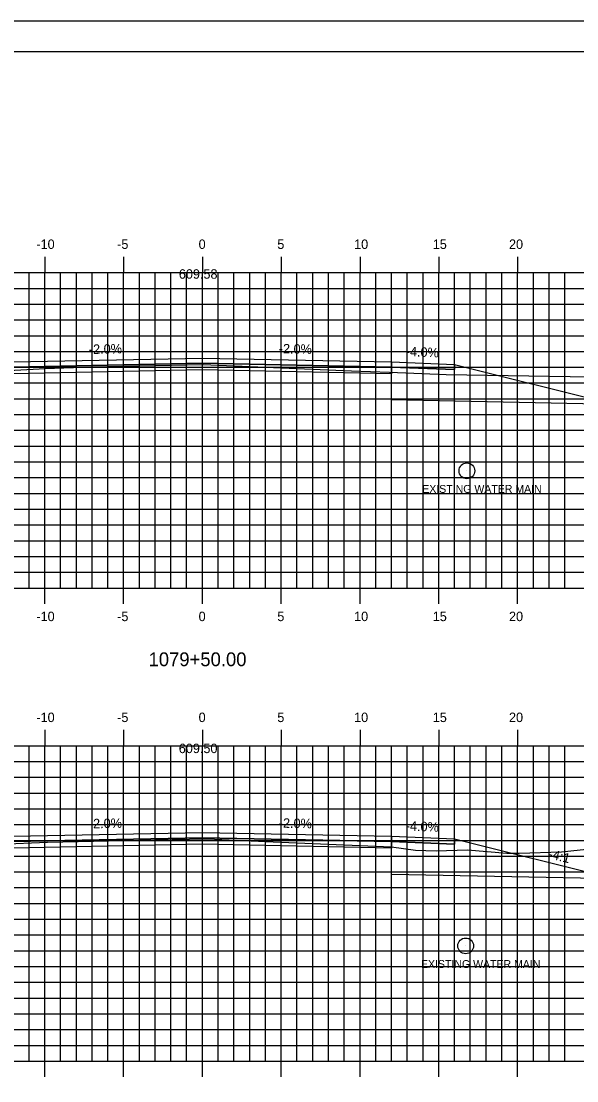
# Model space of a CAD drawing. Extents: x 1070760 to 1070930, y 779716 to 779826.
# Drawn here: x 1070831.4 to 1070866.6, y 779758.5 to 779825.6 of the extents above; entities that cross this region are included whole.
import ezdxf

# ---------------------------------------------------------------- set-up
doc = ezdxf.new("R2010")
doc.units = 0
for name, color, linetype in [('ANNOTATION', 7, 'Continuous'), ('BORDER', 7, 'Continuous'), ('D_Roadway_Centerline', 7, 'Continuous'), ('D_Roadway_Centerline_Text', 7, 'Continuous'), ('D_Roadway_Edge_Pavement', 7, 'Continuous'), ('D_Roadway_Edge_Shoulder', 7, 'Continuous'), ('D_Roadway_Pavement', 7, 'Continuous'), ('D_Roadway_SubGrade', 7, 'Continuous'), ('D_Text_Monospaced', 7, 'Continuous'), ('Existing Water Main', 7, 'Continuous'), ('H_V ANNOTATION', 7, 'Continuous'), ('MAJOR', 7, 'Continuous'), ('MINOR', 7, 'Continuous'), ('PLOT BOUNDARY', 7, 'Continuous'), ('S_Roadway_Centerline', 7, 'Continuous')]:
    doc.layers.add(name, color=color, linetype=linetype)

msp = doc.modelspace()

# ---------------------------------------------------------------- linework, layer by layer
at = {"layer": 'BORDER'}
msp.add_lwpolyline([(1070767.881, 779718.706), (1070927.881, 779718.706), (1070927.881, 779823.706), (1070767.881, 779823.706)], close=True, dxfattribs=at)
at = {"layer": 'D_Roadway_Centerline'}
msp.add_lwpolyline([(1070826.881, 779773.806), (1070830.881, 779773.966), (1070842.881, 779774.206), (1070854.881, 779773.966), (1070858.881, 779773.806)], dxfattribs=at)
at = {"layer": 'D_Roadway_Edge_Pavement'}
for points in [[(1070830.881, 779803.713), (1070830.881, 779804.046), (1070842.881, 779804.286), (1070854.881, 779804.046), (1070854.881, 779803.713), (1070842.881, 779803.953)], [(1070830.881, 779773.633), (1070830.881, 779773.966), (1070842.881, 779774.206), (1070854.881, 779773.966), (1070854.881, 779773.633), (1070842.881, 779773.873)]]:
    msp.add_lwpolyline(points, close=True, dxfattribs=at)
at = {"layer": 'D_Roadway_Edge_Shoulder'}
for points in [[(1070854.881, 779804.046), (1070858.881, 779803.886), (1070858.881, 779803.553), (1070854.881, 779803.713)], [(1070854.881, 779773.966), (1070858.881, 779773.806), (1070858.881, 779773.473), (1070854.881, 779773.633)]]:
    msp.add_lwpolyline(points, close=True, dxfattribs=at)
at = {"layer": 'D_Roadway_Pavement'}
for points in [[(1070830.881, 779803.296), (1070830.881, 779803.713), (1070842.881, 779803.953), (1070854.881, 779803.713), (1070854.881, 779803.296), (1070842.881, 779803.536)], [(1070830.881, 779773.216), (1070830.881, 779773.633), (1070842.881, 779773.873), (1070854.881, 779773.633), (1070854.881, 779773.216), (1070842.881, 779773.456)]]:
    msp.add_lwpolyline(points, close=True, dxfattribs=at)
at = {"layer": 'D_Roadway_SubGrade'}
for points in [[(1070854.881, 779802.213), (1070854.881, 779803.713), (1070854.881, 779803.713), (1070858.881, 779803.553), (1070858.881, 779803.886), (1070869.04, 779801.347), (1070854.881, 779801.63)], [(1070854.881, 779772.133), (1070854.881, 779773.633), (1070854.881, 779773.633), (1070858.881, 779773.473), (1070858.881, 779773.806), (1070869.04, 779771.266), (1070854.881, 779771.549)]]:
    msp.add_lwpolyline(points, close=True, dxfattribs=at)
at = {"layer": 'Existing Water Main'}
for points in [[(1070859.664, 779797.14), (1070859.664, 779797.14)], [(1070859.582, 779767.013), (1070859.582, 779767.013)]]:
    msp.add_lwpolyline(points, dxfattribs=at)
for centre in [(1070859.664, 779797.14), (1070859.582, 779767.013)]:
    msp.add_circle(centre, 0.501, dxfattribs=at)
at = {"layer": 'MAJOR'}
for p, q in [((1070832.881, 779810.708), (1070832.881, 779809.706)), ((1070837.881, 779810.708), (1070837.881, 779809.706)), ((1070842.881, 779810.708), (1070842.881, 779809.706)), ((1070847.881, 779810.708), (1070847.881, 779809.706)), ((1070852.881, 779810.708), (1070852.881, 779809.706)), ((1070857.881, 779810.708), (1070857.881, 779809.706)), ((1070862.881, 779810.708), (1070862.881, 779809.706)), ((1070772.881, 779809.706), (1070912.881, 779809.706)), ((1070772.881, 779809.706), (1070912.881, 779809.706)), ((1070832.881, 779789.706), (1070832.881, 779809.706)), ((1070837.881, 779789.706), (1070837.881, 779809.706)), ((1070842.881, 779789.706), (1070842.881, 779809.706)), ((1070847.881, 779789.706), (1070847.881, 779809.706)), ((1070852.881, 779789.706), (1070852.881, 779809.706)), ((1070857.881, 779789.706), (1070857.881, 779809.706)), ((1070862.881, 779789.706), (1070862.881, 779809.706)), ((1070772.881, 779804.706), (1070912.881, 779804.706)), ((1070772.881, 779799.706), (1070912.881, 779799.706)), ((1070772.881, 779794.706), (1070912.881, 779794.706)), ((1070772.881, 779789.706), (1070912.881, 779789.706)), ((1070772.881, 779789.706), (1070912.881, 779789.706)), ((1070832.881, 779788.704), (1070832.881, 779789.706)), ((1070837.881, 779788.704), (1070837.881, 779789.706)), ((1070842.881, 779788.704), (1070842.881, 779789.706)), ((1070847.881, 779788.704), (1070847.881, 779789.706)), ((1070852.881, 779788.704), (1070852.881, 779789.706)), ((1070857.881, 779788.704), (1070857.881, 779789.706)), ((1070862.881, 779788.704), (1070862.881, 779789.706)), ((1070832.881, 779780.708), (1070832.881, 779779.706)), ((1070837.881, 779780.708), (1070837.881, 779779.706)), ((1070842.881, 779780.708), (1070842.881, 779779.706)), ((1070847.881, 779780.708), (1070847.881, 779779.706)), ((1070852.881, 779780.708), (1070852.881, 779779.706)), ((1070857.881, 779780.708), (1070857.881, 779779.706)), ((1070862.881, 779780.708), (1070862.881, 779779.706)), ((1070772.881, 779779.706), (1070912.881, 779779.706)), ((1070772.881, 779779.706), (1070912.881, 779779.706)), ((1070832.881, 779759.706), (1070832.881, 779779.706)), ((1070837.881, 779759.706), (1070837.881, 779779.706)), ((1070842.881, 779759.706), (1070842.881, 779779.706)), ((1070847.881, 779759.706), (1070847.881, 779779.706)), ((1070852.881, 779759.706), (1070852.881, 779779.706)), ((1070857.881, 779759.706), (1070857.881, 779779.706)), ((1070862.881, 779759.706), (1070862.881, 779779.706)), ((1070772.881, 779774.706), (1070912.881, 779774.706)), ((1070772.881, 779769.706), (1070912.881, 779769.706)), ((1070772.881, 779764.706), (1070912.881, 779764.706)), ((1070772.881, 779759.706), (1070912.881, 779759.706)), ((1070772.881, 779759.706), (1070912.881, 779759.706)), ((1070832.881, 779758.704), (1070832.881, 779759.706)), ((1070837.881, 779758.704), (1070837.881, 779759.706)), ((1070842.881, 779758.704), (1070842.881, 779759.706)), ((1070847.881, 779758.704), (1070847.881, 779759.706)), ((1070852.881, 779758.704), (1070852.881, 779759.706)), ((1070857.881, 779758.704), (1070857.881, 779759.706)), ((1070862.881, 779758.704), (1070862.881, 779759.706))]:
    msp.add_line(p, q, dxfattribs=at)
at = {"layer": 'MINOR'}
for p, q in [((1070831.881, 779789.706), (1070831.881, 779809.706)), ((1070833.881, 779789.706), (1070833.881, 779809.706)), ((1070834.881, 779789.706), (1070834.881, 779809.706)), ((1070835.881, 779789.706), (1070835.881, 779809.706)), ((1070836.881, 779789.706), (1070836.881, 779809.706)), ((1070838.881, 779789.706), (1070838.881, 779809.706)), ((1070839.881, 779789.706), (1070839.881, 779809.706)), ((1070840.881, 779789.706), (1070840.881, 779809.706)), ((1070841.881, 779789.706), (1070841.881, 779809.706)), ((1070843.881, 779789.706), (1070843.881, 779809.706)), ((1070844.881, 779789.706), (1070844.881, 779809.706)), ((1070845.881, 779789.706), (1070845.881, 779809.706)), ((1070846.881, 779789.706), (1070846.881, 779809.706)), ((1070848.881, 779789.706), (1070848.881, 779809.706)), ((1070849.881, 779789.706), (1070849.881, 779809.706)), ((1070850.881, 779789.706), (1070850.881, 779809.706)), ((1070851.881, 779789.706), (1070851.881, 779809.706)), ((1070853.881, 779789.706), (1070853.881, 779809.706)), ((1070854.881, 779789.706), (1070854.881, 779809.706)), ((1070855.881, 779789.706), (1070855.881, 779809.706)), ((1070856.881, 779789.706), (1070856.881, 779809.706)), ((1070858.881, 779789.706), (1070858.881, 779809.706)), ((1070859.881, 779789.706), (1070859.881, 779809.706)), ((1070860.881, 779789.706), (1070860.881, 779809.706)), ((1070861.881, 779789.706), (1070861.881, 779809.706)), ((1070863.881, 779789.706), (1070863.881, 779809.706)), ((1070864.881, 779789.706), (1070864.881, 779809.706)), ((1070865.881, 779789.706), (1070865.881, 779809.706)), ((1070772.881, 779808.706), (1070912.881, 779808.706)), ((1070772.881, 779807.706), (1070912.881, 779807.706)), ((1070772.881, 779806.706), (1070912.881, 779806.706)), ((1070772.881, 779805.706), (1070912.881, 779805.706)), ((1070772.881, 779803.706), (1070912.881, 779803.706)), ((1070772.881, 779802.706), (1070912.881, 779802.706)), ((1070772.881, 779801.706), (1070912.881, 779801.706)), ((1070772.881, 779800.706), (1070912.881, 779800.706)), ((1070772.881, 779798.706), (1070912.881, 779798.706)), ((1070772.881, 779797.706), (1070912.881, 779797.706)), ((1070772.881, 779796.706), (1070912.881, 779796.706)), ((1070772.881, 779795.706), (1070912.881, 779795.706)), ((1070772.881, 779793.706), (1070912.881, 779793.706)), ((1070772.881, 779792.706), (1070912.881, 779792.706)), ((1070772.881, 779791.706), (1070912.881, 779791.706)), ((1070772.881, 779790.706), (1070912.881, 779790.706)), ((1070831.881, 779759.706), (1070831.881, 779779.706)), ((1070833.881, 779759.706), (1070833.881, 779779.706)), ((1070834.881, 779759.706), (1070834.881, 779779.706)), ((1070835.881, 779759.706), (1070835.881, 779779.706)), ((1070836.881, 779759.706), (1070836.881, 779779.706)), ((1070838.881, 779759.706), (1070838.881, 779779.706)), ((1070839.881, 779759.706), (1070839.881, 779779.706)), ((1070840.881, 779759.706), (1070840.881, 779779.706)), ((1070841.881, 779759.706), (1070841.881, 779779.706)), ((1070843.881, 779759.706), (1070843.881, 779779.706)), ((1070844.881, 779759.706), (1070844.881, 779779.706)), ((1070845.881, 779759.706), (1070845.881, 779779.706)), ((1070846.881, 779759.706), (1070846.881, 779779.706)), ((1070848.881, 779759.706), (1070848.881, 779779.706)), ((1070849.881, 779759.706), (1070849.881, 779779.706)), ((1070850.881, 779759.706), (1070850.881, 779779.706)), ((1070851.881, 779759.706), (1070851.881, 779779.706)), ((1070853.881, 779759.706), (1070853.881, 779779.706)), ((1070854.881, 779759.706), (1070854.881, 779779.706)), ((1070855.881, 779759.706), (1070855.881, 779779.706)), ((1070856.881, 779759.706), (1070856.881, 779779.706)), ((1070858.881, 779759.706), (1070858.881, 779779.706)), ((1070859.881, 779759.706), (1070859.881, 779779.706)), ((1070860.881, 779759.706), (1070860.881, 779779.706)), ((1070861.881, 779759.706), (1070861.881, 779779.706)), ((1070863.881, 779759.706), (1070863.881, 779779.706)), ((1070864.881, 779759.706), (1070864.881, 779779.706)), ((1070865.881, 779759.706), (1070865.881, 779779.706)), ((1070772.881, 779778.706), (1070912.881, 779778.706)), ((1070772.881, 779777.706), (1070912.881, 779777.706)), ((1070772.881, 779776.706), (1070912.881, 779776.706)), ((1070772.881, 779775.706), (1070912.881, 779775.706)), ((1070772.881, 779773.706), (1070912.881, 779773.706)), ((1070772.881, 779772.706), (1070912.881, 779772.706)), ((1070772.881, 779771.706), (1070912.881, 779771.706)), ((1070772.881, 779770.706), (1070912.881, 779770.706)), ((1070772.881, 779768.706), (1070912.881, 779768.706)), ((1070772.881, 779767.706), (1070912.881, 779767.706)), ((1070772.881, 779766.706), (1070912.881, 779766.706)), ((1070772.881, 779765.706), (1070912.881, 779765.706)), ((1070772.881, 779763.706), (1070912.881, 779763.706)), ((1070772.881, 779762.706), (1070912.881, 779762.706)), ((1070772.881, 779761.706), (1070912.881, 779761.706)), ((1070772.881, 779760.706), (1070912.881, 779760.706))]:
    msp.add_line(p, q, dxfattribs=at)
at = {"layer": 'PLOT BOUNDARY'}
msp.add_lwpolyline([(1070759.787, 779715.646), (1070929.787, 779715.646), (1070929.787, 779825.646), (1070759.787, 779825.646)], close=True, dxfattribs=at)
at = {"layer": 'S_Roadway_Centerline'}
for points in [[(1070772.881, 779803.721), (1070774.175, 779803.646), (1070777.601, 779803.698), (1070794.884, 779803.789), (1070795.54, 779803.781), (1070795.827, 779803.779), (1070816.237, 779803.59), (1070821.709, 779803.487), (1070822.62, 779803.428), (1070823.003, 779803.302), (1070830.109, 779803.275), (1070830.982, 779803.524), (1070832.895, 779803.63), (1070835.892, 779803.736), (1070842.927, 779803.871), (1070852.337, 779803.482), (1070852.341, 779803.484), (1070854.761, 779803.388), (1070858.356, 779803.244), (1070867.532, 779803.1)], [(1070772.881, 779774.132), (1070773.759, 779774.112), (1070779.811, 779773.957), (1070795.702, 779773.434), (1070799.41, 779773.309), (1070809.871, 779773.41), (1070810.603, 779773.404), (1070817.517, 779773.299), (1070820.921, 779773.247), (1070821.733, 779773.235), (1070830.005, 779773.474), (1070833.041, 779773.581), (1070833.041, 779773.583), (1070839.844, 779773.731), (1070843.179, 779773.795), (1070847.377, 779773.621), (1070854.88, 779773.288), (1070856.403, 779773.079), (1070857.709, 779773.049), (1070859.705, 779773.099), (1070862.196, 779772.901), (1070862.981, 779772.884), (1070865.676, 779772.98), (1070870.023, 779773.443)]]:
    msp.add_lwpolyline(points, dxfattribs=at)

# ---------------------------------------------------------------- texts
at = {"layer": 'ANNOTATION'}
for s, rotation, p in [('-2.0%', 1.14576, (1070835.684, 779804.543)), ('-2.0%', 358.85424, (1070847.724, 779804.59)), ('-4.0%', 357.70939, (1070855.776, 779804.411)), ('-2.0%', 1.14576, (1070835.684, 779774.462)), ('-2.0%', 358.85424, (1070847.724, 779774.51)), ('-4.0%', 357.70939, (1070855.776, 779774.331)), ('-4:1', 345.96376, (1070864.788, 779772.587))]:
    msp.add_text(s, height=0.6, rotation=rotation, dxfattribs=at).set_placement(p)
at = {"layer": 'D_Roadway_Centerline_Text'}
for s, p in [('609.58', (1070841.385, 779809.318)), ('609.50', (1070841.382, 779779.238))]:
    msp.add_text(s, height=0.6, dxfattribs=at).set_placement(p)
at = {"layer": 'D_Text_Monospaced'}
for p in [(1070856.831, 779795.74), (1070856.749, 779765.613)]:
    msp.add_text('EXISTING WATER MAIN', height=0.49998, dxfattribs=at).set_placement(p)
at = {"layer": 'H_V ANNOTATION'}
for s, height, p in [('-10', 0.6, (1070832.345, 779811.206)), ('-5', 0.6, (1070837.471, 779811.206)), ('0', 0.6, (1070842.64, 779811.206)), ('5', 0.6, (1070847.632, 779811.206)), ('10', 0.6, (1070852.506, 779811.206)), ('15', 0.6, (1070857.498, 779811.206)), ('20', 0.6, (1070862.335, 779811.206)), ('-10', 0.6, (1070832.345, 779787.606)), ('-5', 0.6, (1070837.471, 779787.606)), ('0', 0.6, (1070842.64, 779787.606)), ('5', 0.6, (1070847.632, 779787.606)), ('10', 0.6, (1070852.506, 779787.606)), ('15', 0.6, (1070857.498, 779787.606)), ('20', 0.6, (1070862.335, 779787.606)), ('1079+50.00', 0.875, (1070839.463, 779784.749)), ('-10', 0.6, (1070832.345, 779781.206)), ('-5', 0.6, (1070837.471, 779781.206)), ('0', 0.6, (1070842.64, 779781.206)), ('5', 0.6, (1070847.632, 779781.206)), ('10', 0.6, (1070852.506, 779781.206)), ('15', 0.6, (1070857.498, 779781.206)), ('20', 0.6, (1070862.335, 779781.206))]:
    msp.add_text(s, height=height, dxfattribs=at).set_placement(p)

doc.saveas('drawing.dxf')
